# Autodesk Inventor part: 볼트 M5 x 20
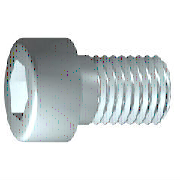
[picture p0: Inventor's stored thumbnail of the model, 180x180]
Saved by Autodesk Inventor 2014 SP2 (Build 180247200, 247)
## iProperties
Created: 2012-02
Part Number: 볼트 M5 x 20
Material: 스테인리스강
Description: 6각 소켓 머리 캡 나사
Document SubType Name: Modeling
Standard: ISO 4762
Designer: mduedu
Standard Revision: Fourth edition 2004-03-01
Standards Organization: ISO
Language: ko-KR
Size Designation: M5 x 20
Categories: <MemberInstance><Categories><Category DisplayName="조임쇠" InternalName="e4da775c-781d-43d5-af7c-5136215cf5a6" Mnemonic="FSTN"><Category DisplayName="볼트" InternalN
Density: 8.08 g/cm^3
Mass: 5.10181 g
Surface Area: 5.88237 cm^2
Volume: 0.631412 cm^3
Appearance: 반광택
IsCustomPart: 0
Author: mduedu
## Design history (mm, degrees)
sketch "스케치1"
  geometry: L1 (-1.167, 0)-(20, 0); L2 (20, 0)-(20, 2.5); L3 (20, 2.5)-(2, 2.5); L4 (2, 2.5)-(1.509, 2.5); L5 (1.509, 2.5)-(0, 2.5); L6 (0, 2.5)-(0, 4.25); L7 (0, 4.25)-(-5, 4.25); L8 (-5, 4.25)-(-5, 2.309); L9 (-5, 2.309)-(-2.5, 2.309); L10 (-2.5, 2.309)-(-1.167, 0); L11 (-10, 0)-(25, 0) reference; L12 (0, -0.85)-(0, 5.1) reference; L13 (2, 2.5)-(0, 2.5)
  constraints: 22 end point, 6 parallel, 2 collinear, 2 perpendicular, 1 horizontal, 1 point on line
  dimensions: "d1" = 18 distance from line of L3.end L2 (= GEL); "d2" = 0.49086 distance of L4.end L3.end (computed from GAL); "d3" = 5 distance between parallel lines of L8 L6 (= KOH); "d4" = 2.5 distance of L8.end L9.end (= INTI); "d5" = 60 deg angle of L10 L1; "d6" = 5 diameter of L3 L1 (= GD); "d7" = 5 diameter of L5 L1 (= BDM); "d8" = 4.6188 diameter of L9 L1 (= 1.1547 x SW); "d9" = 8.5 diameter of L7 L1 (= KOD); "d26" = 20 distance between parallel lines of L12 L2 (= NLG)
revolve "본체" sketch "스케치1" stored, may be unused: angle "d10" = 90 deg
sketch "스케치2"
  geometry: L1 (0, -5.95)-(0, 5.95) reference; L2 (-5.95, 0)-(5.95, 0) reference; L3 (2.309, 0)-(1.155, -2); L4 (1.155, -2)-(-1.155, -2); L5 (-1.155, -2)-(-2.309, 0); L6 (-2.309, 0)-(-1.155, 2); L7 (-1.155, 2)-(1.155, 2); L8 (1.155, 2)-(2.309, 0); 2 further points
  constraints: 12 end point, 1 coincident, 1 horizontal alignment, 1 point on line, 12 other
extrude "슬롯" join sketch "스케치2" stored distance "d11" = 10; taper "d12" = 0 deg
workplane "Work Plane1"
fillet "Fillet2" dims "d30" = 0.1 (= R)
body "Solid1"
fillet "모깎기1" dims "d17" = 0.5 (= RR)
feature "스레드" dims "d13" = 18 (= GEL), "d14" = 0
chamfer "모따기1" distance "d15" = 0.49076 (= -0.5 x SPD + 0.5 x GD); stored, may be unused: second distance "d16" = 0.49076 (= GUL), angle "d27" = 45 deg
other parameters: "GD" = 5 [user parameter; used in 2 equation terms], "NLG" = 20 [user parameter; used in 1 equation term], "GEL" = 18 [user parameter; used in 2 equation terms], "KOD" = 8.5 [user parameter; used in 1 equation term], "KOH" = 5 [user parameter; used in 1 equation term], "INTI" = 2.5 [user parameter; used in 1 equation term], "GAL" = 0.49076 (= 0.61345 x PTC) [user parameter; used in 1 equation term], "GUL" = 0.49076 (= 0.61345 x PTC) [user parameter; used in 1 equation term], "BDM" = 5 (= NND) [user parameter; used in 1 equation term], "SW" = 4 [user parameter; used in 2 equation terms], "RR" = 0.5 [user parameter; used in 1 equation term], "SPD" = 4.01848 (= NND - 1.2269 x PTC) [user parameter; used in 1 equation term], "d19" = 0, "d28" = 0, "d29" = 0, "R" = 0.1 [user parameter; used in 1 equation term], "TOA" = 30 deg [user parameter], "GD1" = 4.01848 (= THREADDIA - 1.2269 x PTC) [user parameter], "THREADDIA" = 5 [user parameter; used in 1 equation term], "FAWI" = 45 deg [user parameter], "TPU" = 12.5 (computed from PTC) [user parameter], "PTC" = 0.8 [user parameter; used in 5 equation terms], "NND" = 5 [user parameter; used in 2 equation terms], "E0" = 4.62 (= 1.155 x SW) [user parameter]
